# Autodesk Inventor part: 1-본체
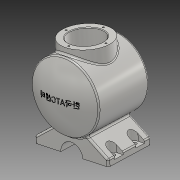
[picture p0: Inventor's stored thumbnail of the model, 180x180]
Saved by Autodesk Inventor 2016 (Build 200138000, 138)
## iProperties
Created: 2017-04
Part Number: 1-본체
Material: 알루미늄 6061
Document SubType Name: Modeling
Designer: CAMTIC
Density: 2.7 g/cm^3
Appearance: 알루미늄 - 평지
Mass: 1966.6 g
Surface Area: 1089.79 cm^2
Volume: 728.369 cm^3
Author: CAMTIC
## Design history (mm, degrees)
sketch "스케치2"
  geometry: L1 (38, 62)-(0, 62); L2 (0, 62)-(0, -58); L3 (55, -43.712)-(55, 50); L4 (38, 62)-(38, 50); L5 (38, 50)-(55, 50); A1 r 113 centre (0, 55) between (0, -58) and (55, -43.712); 1 further point
  constraints: 10 end point, 2 perpendicular, 2 point on circle, 2 point on line, 1 centre point, 1 horizontal, 1 parallel
  dimensions: "d1" = 113 radius of A1; "d2" = 110 diameter of L3 L2; "d3" = 12 distance of L1.start L4.end; "d4" = 50 distance from line of point (0, 0) L5; "d5" = 76 diameter of L4 L2; "d6" = 108 distance from line of L2.end L5
revolve "회전1" sketch "스케치2" stored, may be unused: angle "d7" = 90 deg
sketch "스케치3"
  geometry: L1 (-60, -82)-(60, -82); L2 (60, -82)-(60, -72); L3 (60, -72)-(26.221, -48.347); L4 (-60, -82)-(-60, -72); L5 (-60, -72)-(-26.221, -48.347); A1 r 55 centre (0, 0) between (-26.221, -48.347) and (26.221, -48.347) reference; 2 further points
  constraints: 10 end point, 2 point on circle, 1 equal length, 1 horizontal, 1 midpoint, 1 perpendicular, 1 vertical, 1 vertical alignment
  dimensions: "d8" = 120 distance of L1.start L1.end; "d9" = 55 deg angle of L4 L5; "d10" = 55 deg angle of L2 L3 (= d9); "d11" = 10 distance of L1.end L2.end; "d12" = 82 distance from line of point (0, 0) L1
extrude "돌출1" join sketch "스케치3" distance "d13" = 42; taper "d14" = 0 deg; dims "d103" = 38, "d104" = 0
sketch "스케치4"
  geometry: C1 r 38 at (0, 0); 1 further point
  constraints: 1 centre point, 1 coincident
  dimensions: "d15" = 76 diameter of C1
extrude "돌출2" join sketch "스케치4" distance "d16" = 65; taper "d17" = 0 deg
sketch "스케치5"
  geometry: L1 (40, 40)-(0, 40); L2 (0, 40)-(0, -48); L3 (40, 40)-(40, -39.916); L4 (-38, 62)-(38, 62) reference; A1 r 113 centre (0, 55) between (-55, -43.712) and (55, -43.712) reference; A2 r 103 centre (0, 55) between (0, -48) and (40, -39.916); 1 further point
  constraints: 6 end point, 2 point on circle, 1 centre point, 1 horizontal, 1 perpendicular, 1 point on line, 1 vertical
  dimensions: "d18" = 10 radial gap between concentric circles of A1 A2; "d19" = 80 diameter of L3 L2; "d20" = 22 distance between parallel lines of L4 L1
revolve "회전2" sketch "스케치5" stored, may be unused: angle "d21" = 90 deg
hole "구멍1" diameter "d24" = 54; stored, may be unused: countersink angle "d28" = 90 deg, drill point angle "d30" = 118 deg; dims "d22" = 10, "d23" = 10, "d25" = 6, "d26" = 4, "d27" = 2, "d29" = 8
fillet "모깎기2" dims "d35" = 3
chamfer "모따기2" distance "d36" = 1; stored, may be unused: second distance "d37" = 2, angle "d38" = 45 deg
hole "구멍2" diameter "d41" = 54; stored, may be unused: countersink angle "d45" = 90 deg, drill point angle "d47" = 118 deg; dims "d39" = 10, "d40" = 10, "d42" = 6, "d43" = 4, "d44" = 2, "d46" = 8
chamfer "모따기3" distance "d48" = 1; stored, may be unused: second distance "d49" = 2, angle "d50" = 45 deg
chamfer "모따기4" distance "d51" = 1; stored, may be unused: second distance "d52" = 2, angle "d53" = 45 deg
fillet "모깎기3" dims "d54" = 3
sketch "스케치6" dims "d55" = 65
  geometry: L1 (0, 0)-(-32.5, 0); 1 further point
  constraints: 2 end point, 1 coincident, 1 horizontal, 1 horizontal alignment, 2 other
hole "구멍3" sketch "스케치6" at (-32.5, 0) diameter "d56" = 3.242; stored, may be unused: countersink angle "d60" = 90 deg, drill point angle "d62" = 118 deg; dims "d57" = 8, "d58" = 4, "d59" = 2, "d61" = 10
sketch "스케치7" dims "d66" = 65
  geometry: L1 (0, 0)-(0, 32.5); 1 further point
  constraints: 2 end point, 1 coincident, 1 vertical, 1 vertical alignment, 2 other
hole "구멍4" sketch "스케치7" at (0, 32.5) diameter "d67" = 3.242; stored, may be unused: countersink angle "d71" = 90 deg, drill point angle "d73" = 118 deg; dims "d68" = 8, "d69" = 4, "d70" = 2, "d72" = 10
fillet "모깎기4" dims "d77" = 3
sketch "스케치8"
  geometry: L1 (-60, -82)-(60, -82) reference; C1 r 18 at (0, -82); 2 further points
  constraints: 1 centre point, 1 coincident, 1 midpoint
  dimensions: "d78" = 18 radius of C1
extrude "돌출3" cut sketch "스케치8" stored distance "d79" = 10; taper "d80" = 0 deg
node "작업 평면1"
sketch "스케치9" dims "d83" = 8
  geometry: L1 (-60, -41.144)-(-60, 38.856) reference; L2 (-26.221, -41.144)-(-60, -41.144) reference; L3 (60, -41.144)-(26.221, -41.144) reference; L4 (60, -41.144)-(60, 38.856) reference; L5 (26.221, 38.856)-(60, 38.856) reference; L6 (-60, 38.856)-(-26.221, 38.856) reference; L7 (-50, 10.856)-(-60, 10.856); L8 (-60, 10.856)-(-60, 26.856); L9 (-60, 26.856)-(-50, 26.856); L10 (-50, 26.856)-(-50, 10.856); L11 (-8.19, -1.144)-(-85.004, -1.144); 2 further points
  constraints: 10 end point, 2 horizontal, 2 parallel, 1 collinear, 1 midpoint, 1 perpendicular, 1 vertical alignment, 2 other
  dimensions: "d84" = 10 distance between parallel lines of L1 L10; "d105" = 40 distance between parallel lines of L6 L11; "d106" = 20 distance from line of point (-50, 18.856) L11
extrude "돌출4" cut sketch "스케치9" distance "d86" = 21; taper "d87" = 0 deg
hole "구멍5" diameter "d90" = 8; stored, may be unused: countersink angle "d94" = 90 deg, drill point angle "d96" = 118 deg; dims "d88" = 10, "d89" = 10, "d91" = 8, "d92" = 4, "d93" = 2, "d95" = 10
fillet "모깎기5" dims "d100" = 3
fillet "모깎기6" dims "d101" = 3
fillet "모깎기7" dims "d102" = 3
fillet "모깎기8" dims "d107" = 3
node "작업 평면3"
sketch "스케치23"
  geometry: 2 further points
  constraints: 1 coincident, 1 other
feature "엠보싱2" sketch "스케치23" dims "d1" = 113, "d2" = 110, "d3" = 12, "d4" = 50, "d5" = 76, "d6" = 108, "d15" = 76, "d110" = 0.5, "d111" = 0
node "솔리드1"
pattern_circular "원형 패턴1" dims angle "d64" = 360 deg
pattern_circular "원형 패턴2" dims angle "d75" = 360 deg
pattern_linear "직사각형 패턴1"
mirror "대칭1"
